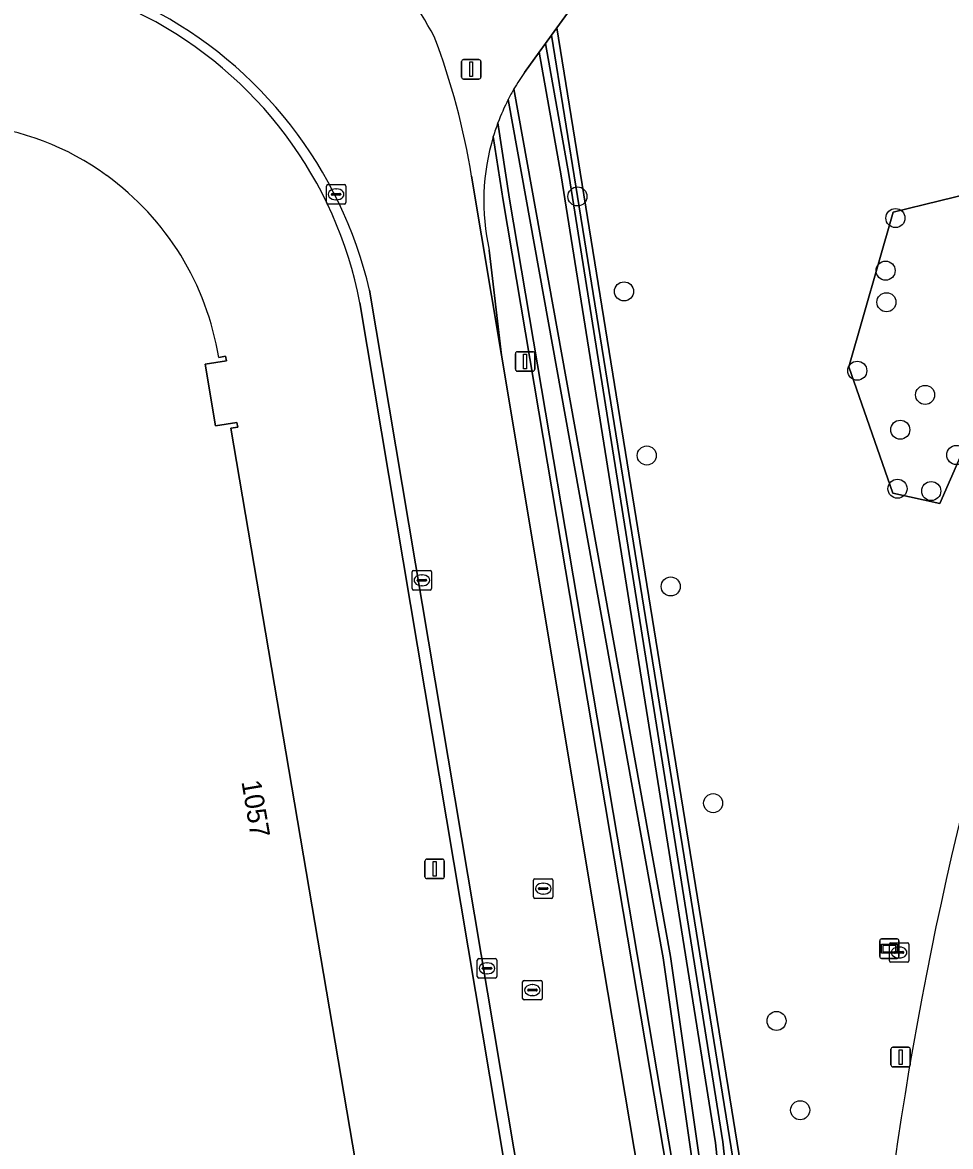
# Model space of a CAD drawing. Extents: x 154324 to 155744, y 382937 to 384188.
# Drawn here: x 154972.4 to 155020, y 383822.2 to 383879.9 of the extents above; entities that cross this region are included whole.
import ezdxf

# ---------------------------------------------------------------- set-up
doc = ezdxf.new("R2010")
doc.units = 0
for name, color, linetype in [('IMGEO_Boom', 7, 'Continuous'), ('IMGEO_Brandkraan', 7, 'Continuous'), ('IMGEO_Fietspad_gesloten', 7, 'Continuous'), ('IMGEO_Gemengd_bos', 7, 'Continuous'), ('IMGEO_Groenvoorziening', 7, 'Continuous'), ('IMGEO_Kolk', 7, 'Continuous'), ('IMGEO_Lichtmast', 7, 'Continuous'), ('IMGEO_Loofbos', 7, 'Continuous'), ('IMGEO_Oever', 7, 'Continuous'), ('IMGEO_Pand', 7, 'Continuous'), ('IMGEO_Pand_nummerreeks', 7, 'Continuous'), ('IMGEO_Rijbaan_lokaal_gesloten', 7, 'Continuous'), ('IMGEO_Rijbaan_lokaal_open', 7, 'Continuous'), ('IMGEO_Rioolput', 7, 'Continuous'), ('IMGEO_Verklikker', 7, 'Continuous'), ('IMGEO_Voetpad_open', 7, 'Continuous'), ('IMGEO_Waterloop', 7, 'Continuous')]:
    doc.layers.add(name, color=color, linetype=linetype)

msp = doc.modelspace()

# ---------------------------------------------------------------- linework, layer by layer
at = {"layer": 'IMGEO_Boom'}
for centre in [(155000.837, 383870.939), (155017.141, 383869.83), (155016.636, 383867.133), (155003.225, 383866.07), (155016.679, 383865.514), (155015.183, 383862.004), (155018.661, 383860.763), (155017.388, 383858.977), (155004.392, 383857.656), (155020.259, 383857.681), (155017.246, 383855.953), (155018.975, 383855.834), (155005.618, 383850.94), (155007.794, 383839.829), (155011.045, 383828.66), (155012.255, 383824.082)]:
    msp.add_circle(centre, 0.489, dxfattribs=at)
at = {"layer": 'IMGEO_Brandkraan'}
for p, q in [((155016.828, 383831.745), (155016.828, 383832.597)), ((155016.903, 383832.671), (155017.755, 383832.671)), ((155017.829, 383832.597), (155017.829, 383831.745)), ((155017.087, 383832.165), (155017.087, 383832.177)), ((155017.525, 383832.128), (155017.127, 383832.128)), ((155017.13, 383832.214), (155017.528, 383832.214)), ((155017.316, 383832.451), (155017.341, 383832.451)), ((155017.571, 383832.177), (155017.571, 383832.165)), ((155017.755, 383831.671), (155016.903, 383831.671)), ((155017.339, 383831.891), (155017.314, 383831.891))]:
    msp.add_line(p, q, dxfattribs=at)
for points in [[(155016.828, 383831.745), (155016.828, 383832.597)], [(155016.903, 383832.671), (155017.755, 383832.671)], [(155017.829, 383832.597), (155017.829, 383831.745)], [(155017.755, 383831.671), (155016.903, 383831.671)]]:
    msp.add_lwpolyline(points, dxfattribs=at)
for centre, radius, start, end in [((155016.905, 383832.595), 0.0765, 91.55205, 178.44795), ((155016.905, 383832.595), 0.0765, 91.55205, 178.44795), ((155017.753, 383832.595), 0.0765, 1.55205, 88.44795), ((155017.753, 383832.595), 0.0765, 1.55205, 88.44795), ((155017.127, 383832.174), 0.0403, 85.87752, 175.75265), ((155017.124, 383832.164), 0.0366, 178.93798, 274.71019), ((155017.528, 383832.171), 0.043, 264.86636, 352.45326), ((155017.532, 383832.176), 0.0386, 1.73085, 96.63898), ((155016.905, 383831.747), 0.0765, 181.55205, 268.44795), ((155016.905, 383831.747), 0.0765, 181.55205, 268.44795), ((155017.753, 383831.747), 0.0765, 271.55205, 358.44795), ((155017.753, 383831.747), 0.0765, 271.55205, 358.44795)]:
    msp.add_arc(centre, radius, start, end, dxfattribs=at)
for centre, major_axis, ratio, start_param, end_param in [((155017.315, 383832.171), (-0.387, 0.002), 0.722429, 4.712389, 7.853982), ((155017.34, 383832.171), (-0.39, 0.002), 0.717154, 1.570796, 4.712389)]:
    msp.add_ellipse(centre, major_axis=major_axis, ratio=ratio, start_param=start_param, end_param=end_param, dxfattribs=at)
at = {"layer": 'IMGEO_Fietspad_gesloten'}
for centre, radius, start, end in [((155068.256, 383897.466), 48.743, 181.03851, 207.95634), ((155205.608, 383794.513), 190.42, 159.9547, 171.93294)]:
    msp.add_arc(centre, radius, start, end, dxfattribs=at)
at = {"layer": 'IMGEO_Gemengd_bos'}
for points in [[(155007.915, 383822.409), (155000.011, 383871.994), (154998.88, 383878.344), (154998.126, 383877.302)], [(154997.582, 383876.452), (155005.612, 383831.964), (155009.111, 383807.437), (155008.833, 383813.728), (155008.825, 383813.835), (155007.915, 383822.409)]]:
    msp.add_lwpolyline(points, dxfattribs=at)
msp.add_arc((155007.047, 383870.993), 10.927, 144.73392, 150.02759, dxfattribs=at)
at = {"layer": 'IMGEO_Groenvoorziening'}
for points in [[(155004.825, 383886.546), (155002.919, 383883.925), (155001.914, 383882.537), (154999.781, 383879.589), (155010.405, 383813.833), (155010.749, 383800.586)], [(155008.779, 383799.869), (155006.822, 383812.702), (154997.022, 383870.738), (154996.525, 383874.017)], [(154996.312, 383868.192), (154996.943, 383862.793), (155002.174, 383831.432), (155007.976, 383797.016), (155010.285, 383783.102), (155010.136, 383783.072), (155013.373, 383763.974), (155014.065, 383763.349), (155014.521, 383763.048)]]:
    msp.add_lwpolyline(points, dxfattribs=at)
msp.add_lwpolyline([(155025.672, 383869.465), (155019.414, 383855.191), (155016.999, 383855.716), (155014.751, 383862.196), (155017.019, 383870.138), (155024.143, 383871.87)], close=True, dxfattribs=at)
for centre, radius, start, end in [((155068.256, 383897.466), 48.743, 181.03851, 207.95634), ((155007.497, 383870.699), 11.462, 163.17576, 192.63589), ((155205.608, 383794.513), 190.42, 159.9547, 171.93294)]:
    msp.add_arc(centre, radius, start, end, dxfattribs=at)
at = {"layer": 'IMGEO_Kolk'}
for p, q in [((154987.965, 383870.621), (154987.965, 383871.473)), ((154988.04, 383871.547), (154988.892, 383871.547)), ((154988.453, 383871.327), (154988.478, 383871.327)), ((154988.966, 383871.473), (154988.966, 383870.621)), ((154988.892, 383870.547), (154988.04, 383870.547)), ((154988.224, 383871.041), (154988.224, 383871.053)), ((154988.662, 383871.004), (154988.264, 383871.004)), ((154988.267, 383871.09), (154988.665, 383871.09)), ((154988.476, 383870.767), (154988.451, 383870.767)), ((154988.708, 383871.053), (154988.708, 383871.041)), ((154992.361, 383850.831), (154992.361, 383851.683)), ((154992.436, 383851.757), (154993.288, 383851.757)), ((154992.849, 383851.537), (154992.874, 383851.537)), ((154993.362, 383851.683), (154993.362, 383850.831)), ((154992.62, 383851.251), (154992.62, 383851.263)), ((154993.058, 383851.214), (154992.66, 383851.214)), ((154992.663, 383851.3), (154993.061, 383851.3)), ((154992.872, 383850.977), (154992.847, 383850.977)), ((154993.104, 383851.263), (154993.104, 383851.251)), ((154993.288, 383850.757), (154992.436, 383850.757)), ((154995.701, 383830.932), (154995.701, 383831.784)), ((154995.776, 383831.858), (154996.628, 383831.858)), ((154995.96, 383831.352), (154995.96, 383831.364)), ((154996.003, 383831.401), (154996.401, 383831.401)), ((154996.189, 383831.638), (154996.214, 383831.638)), ((154996.444, 383831.364), (154996.444, 383831.352)), ((154996.702, 383831.784), (154996.702, 383830.932)), ((154996.628, 383830.858), (154995.776, 383830.858)), ((154996.398, 383831.315), (154996, 383831.315)), ((154996.212, 383831.078), (154996.187, 383831.078))]:
    msp.add_line(p, q, dxfattribs=at)
for points in [[(154987.965, 383870.621), (154987.965, 383871.473)], [(154988.04, 383871.547), (154988.892, 383871.547)], [(154988.966, 383871.473), (154988.966, 383870.621)], [(154988.892, 383870.547), (154988.04, 383870.547)], [(154992.361, 383850.831), (154992.361, 383851.683)], [(154992.436, 383851.757), (154993.288, 383851.757)], [(154993.362, 383851.683), (154993.362, 383850.831)], [(154993.288, 383850.757), (154992.436, 383850.757)], [(154995.701, 383830.932), (154995.701, 383831.784)], [(154995.776, 383831.858), (154996.628, 383831.858)], [(154996.702, 383831.784), (154996.702, 383830.932)], [(154996.628, 383830.858), (154995.776, 383830.858)]]:
    msp.add_lwpolyline(points, dxfattribs=at)
for centre, radius, start, end in [((154988.042, 383871.471), 0.0765, 91.55205, 178.44795), ((154988.042, 383871.471), 0.0765, 91.55205, 178.44795), ((154988.89, 383871.471), 0.0765, 1.55205, 88.44795), ((154988.89, 383871.471), 0.0765, 1.55205, 88.44795), ((154988.042, 383870.623), 0.0765, 181.55205, 268.44795), ((154988.042, 383870.623), 0.0765, 181.55205, 268.44795), ((154988.264, 383871.05), 0.0403, 85.87752, 175.75265), ((154988.261, 383871.04), 0.0366, 178.93798, 274.71019), ((154988.665, 383871.047), 0.043, 264.86636, 352.45326), ((154988.669, 383871.052), 0.0386, 1.73085, 96.63898), ((154988.89, 383870.623), 0.0765, 271.55205, 358.44795), ((154988.89, 383870.623), 0.0765, 271.55205, 358.44795), ((154992.438, 383851.681), 0.0765, 91.55205, 178.44795), ((154992.438, 383851.681), 0.0765, 91.55205, 178.44795), ((154993.286, 383851.681), 0.0765, 1.55205, 88.44795), ((154993.286, 383851.681), 0.0765, 1.55205, 88.44795), ((154992.66, 383851.26), 0.0403, 85.87752, 175.75265), ((154992.657, 383851.25), 0.0366, 178.93798, 274.71019), ((154993.061, 383851.257), 0.043, 264.86636, 352.45326), ((154993.065, 383851.262), 0.0386, 1.73085, 96.63898), ((154992.438, 383850.833), 0.0765, 181.55205, 268.44795), ((154992.438, 383850.833), 0.0765, 181.55205, 268.44795), ((154993.286, 383850.833), 0.0765, 271.55205, 358.44795), ((154993.286, 383850.833), 0.0765, 271.55205, 358.44795), ((154995.778, 383831.782), 0.0765, 91.55205, 178.44795), ((154995.778, 383831.782), 0.0765, 91.55205, 178.44795), ((154996, 383831.361), 0.0403, 85.87752, 175.75265), ((154995.997, 383831.351), 0.0366, 178.93798, 274.71019), ((154996.401, 383831.358), 0.043, 264.86636, 352.45326), ((154996.405, 383831.363), 0.0386, 1.73085, 96.63898), ((154996.626, 383831.782), 0.0765, 1.55205, 88.44795), ((154996.626, 383831.782), 0.0765, 1.55205, 88.44795), ((154995.778, 383830.934), 0.0765, 181.55205, 268.44795), ((154995.778, 383830.934), 0.0765, 181.55205, 268.44795), ((154996.626, 383830.934), 0.0765, 271.55205, 358.44795), ((154996.626, 383830.934), 0.0765, 271.55205, 358.44795)]:
    msp.add_arc(centre, radius, start, end, dxfattribs=at)
for centre, major_axis, ratio, start_param, end_param in [((154988.452, 383871.047), (-0.387, 0.002), 0.722429, 4.712389, 7.853982), ((154988.477, 383871.047), (-0.39, 0.002), 0.717154, 1.570796, 4.712389), ((154992.848, 383851.257), (-0.387, 0.002), 0.722429, 4.712389, 7.853982), ((154992.873, 383851.257), (-0.39, 0.002), 0.717154, 1.570796, 4.712389), ((154996.188, 383831.358), (-0.387, 0.002), 0.722429, 4.712389, 7.853982), ((154996.213, 383831.358), (-0.39, 0.002), 0.717154, 1.570796, 4.712389)]:
    msp.add_ellipse(centre, major_axis=major_axis, ratio=ratio, start_param=start_param, end_param=end_param, dxfattribs=at)
at = {"layer": 'IMGEO_Lichtmast'}
for p, q in [((154994.895, 383877.06), (154994.895, 383877.86)), ((154994.895, 383877.86), (154994.895, 383877.06)), ((154994.995, 383877.96), (154995.785, 383877.96)), ((154995.785, 383877.96), (154994.995, 383877.96)), ((154995.885, 383877.86), (154995.885, 383877.06)), ((154995.885, 383877.06), (154995.885, 383877.86)), ((154995.785, 383876.96), (154994.995, 383876.96)), ((154994.995, 383876.96), (154995.785, 383876.96)), ((154997.661, 383862.076), (154997.661, 383862.876)), ((154997.661, 383862.876), (154997.661, 383862.076)), ((154997.761, 383862.976), (154998.551, 383862.976)), ((154998.551, 383862.976), (154997.761, 383862.976)), ((154998.651, 383862.876), (154998.651, 383862.076)), ((154998.651, 383862.076), (154998.651, 383862.876)), ((154998.551, 383861.976), (154997.761, 383861.976)), ((154997.761, 383861.976), (154998.551, 383861.976)), ((154993.022, 383836.057), (154993.022, 383836.857)), ((154993.022, 383836.857), (154993.022, 383836.057)), ((154993.122, 383836.957), (154993.912, 383836.957)), ((154993.912, 383836.957), (154993.122, 383836.957)), ((154994.012, 383836.857), (154994.012, 383836.057)), ((154994.012, 383836.057), (154994.012, 383836.857)), ((154993.912, 383835.957), (154993.122, 383835.957)), ((154993.122, 383835.957), (154993.912, 383835.957)), ((155017.012, 383827.308), (155017.802, 383827.308)), ((155017.802, 383827.308), (155017.012, 383827.308)), ((155016.912, 383826.408), (155016.912, 383827.208)), ((155016.912, 383827.208), (155016.912, 383826.408)), ((155017.902, 383827.208), (155017.902, 383826.408)), ((155017.902, 383826.408), (155017.902, 383827.208)), ((155017.802, 383826.308), (155017.012, 383826.308)), ((155017.012, 383826.308), (155017.802, 383826.308))]:
    msp.add_line(p, q, dxfattribs=at)
for points in [[(154995.315, 383877.835), (154995.465, 383877.835), (154995.465, 383877.085), (154995.315, 383877.085), (154995.315, 383877.835)], [(154998.081, 383862.851), (154998.231, 383862.851), (154998.231, 383862.101), (154998.081, 383862.101), (154998.081, 383862.851)], [(154993.442, 383836.832), (154993.592, 383836.832), (154993.592, 383836.082), (154993.442, 383836.082), (154993.442, 383836.832)], [(155017.332, 383827.183), (155017.482, 383827.183), (155017.482, 383826.433), (155017.332, 383826.433), (155017.332, 383827.183)]]:
    msp.add_lwpolyline(points, dxfattribs=at)
for centre, start, end in [((154994.995, 383877.86), 90, 180), ((154994.995, 383877.86), 90, 180), ((154995.785, 383877.86), 0, 90), ((154995.785, 383877.86), 360, 90), ((154994.995, 383877.06), 180, 270), ((154994.995, 383877.06), 180, 270), ((154995.785, 383877.06), 270, 0), ((154995.785, 383877.06), 270, 0), ((154997.761, 383862.876), 90, 180), ((154997.761, 383862.876), 90, 180), ((154998.551, 383862.876), 0, 90), ((154998.551, 383862.876), 360, 90), ((154997.761, 383862.076), 180, 270), ((154997.761, 383862.076), 180, 270), ((154998.551, 383862.076), 270, 0), ((154998.551, 383862.076), 270, 0), ((154993.122, 383836.857), 90, 180), ((154993.122, 383836.857), 90, 180), ((154993.912, 383836.857), 0, 90), ((154993.912, 383836.857), 360, 90), ((154993.122, 383836.057), 180, 270), ((154993.122, 383836.057), 180, 270), ((154993.912, 383836.057), 270, 0), ((154993.912, 383836.057), 270, 0), ((155017.012, 383827.208), 90, 180), ((155017.012, 383827.208), 90, 180), ((155017.802, 383827.208), 0, 90), ((155017.802, 383827.208), 360, 90), ((155017.012, 383826.408), 180, 270), ((155017.012, 383826.408), 180, 270), ((155017.802, 383826.408), 270, 0), ((155017.802, 383826.408), 270, 0)]:
    msp.add_arc(centre, 0.1, start, end, dxfattribs=at)
at = {"layer": 'IMGEO_Loofbos'}
msp.add_lwpolyline([(155025.672, 383869.465), (155024.143, 383871.87), (155017.019, 383870.138), (155014.751, 383862.196), (155016.999, 383855.716), (155019.414, 383855.191)], close=True, dxfattribs=at)
at = {"layer": 'IMGEO_Oever'}
for points in [[(155010.749, 383800.586), (155010.405, 383813.833), (154999.781, 383879.589), (154999.501, 383879.202), (155000.837, 383870.939), (155010.067, 383813.801), (155010.409, 383800.612)], [(154997.285, 383875.907), (155005.228, 383831.902), (155008.867, 383806.395), (155009.545, 383806.425), (155009.221, 383813.751), (155009.212, 383813.87), (155008.3, 383822.46), (155000.394, 383872.059), (154999.197, 383878.781), (154998.88, 383878.344), (155000.011, 383871.994), (155007.915, 383822.409), (155008.825, 383813.835), (155008.833, 383813.728), (155009.111, 383807.437), (155005.612, 383831.964), (154997.582, 383876.452)], [(155009.11, 383799.946), (155007.157, 383812.756), (154997.357, 383870.792), (154996.761, 383874.717)], [(154996.525, 383874.017), (154997.022, 383870.738), (155006.822, 383812.702), (155008.779, 383799.869)]]:
    msp.add_lwpolyline(points, dxfattribs=at)
for centre, radius, start, end in [((155008.585, 383870.102), 12.704, 150.01187, 152.81142), ((155006.86, 383870.922), 10.788, 159.40686, 163.3308)]:
    msp.add_arc(centre, radius, start, end, dxfattribs=at)
at = {"layer": 'IMGEO_Pand'}
for points in [[(154962.788, 383873.403), (154930.221, 383858.416), (154936.2, 383845.476), (154938.531, 383840.433), (154922.044, 383832.788), (154921.562, 383832.565), (154925.972, 383806.919), (154925.989, 383806.82), (154990.078, 383817.772), (154990.053, 383817.92), (154983.065, 383859.056)], [(154983.065, 383859.056), (154983.42, 383859.114), (154983.382, 383859.351), (154982.276, 383859.173), (154981.758, 383862.33), (154982.843, 383862.511), (154982.803, 383862.747), (154982.447, 383862.688)]]:
    msp.add_lwpolyline(points, dxfattribs=at)
for centre, radius, start, end in [((154968.564, 383860.875), 13.795, 53.84566, 114.75354), ((154968.262, 383860.383), 14.371, 9.2287, 54.03016)]:
    msp.add_arc(centre, radius, start, end, dxfattribs=at)
at = {"layer": 'IMGEO_Rijbaan_lokaal_gesloten'}
for points in [[(154998.126, 383877.302), (154998.88, 383878.344), (154999.197, 383878.781), (154999.501, 383879.202), (154999.781, 383879.589), (155001.914, 383882.537), (155002.919, 383883.925), (155004.825, 383886.546)], [(154990.18, 383866.132), (155008.692, 383756.004), (155014.572, 383756.911), (155014.481, 383757.434), (155013.373, 383763.974), (155010.136, 383783.072), (155010.285, 383783.102), (155007.976, 383797.016), (155002.174, 383831.432), (154996.943, 383862.793), (154995.411, 383871.976)], [(154995.411, 383871.976), (154996.943, 383862.793), (154996.312, 383868.192)]]:
    msp.add_lwpolyline(points, dxfattribs=at)
for centre, radius, start, end in [((154973.044, 383868.176), 23.201, 28.19104, 41.12856), ((154973.044, 383868.176), 23.201, 28.19104, 41.12856), ((154968.895, 383861.158), 21.858, 13.15331, 112.43509), ((154959.519, 383866.198), 36.354, 9.14486, 20.84743), ((154959.519, 383866.198), 36.354, 9.14486, 20.84743), ((155007.047, 383870.993), 10.927, 144.73392, 150.02759), ((155008.585, 383870.102), 12.704, 150.01187, 152.81142), ((155007.312, 383870.781), 11.261, 152.92472, 159.54403), ((155006.86, 383870.922), 10.788, 159.40686, 163.3308), ((155007.497, 383870.699), 11.462, 163.17576, 192.63589)]:
    msp.add_arc(centre, radius, start, end, dxfattribs=at)
at = {"layer": 'IMGEO_Rijbaan_lokaal_open'}
msp.add_lwpolyline([(154989.689, 383865.488), (154997.464, 383819.179), (155002.093, 383791.612), (155006.354, 383766.232), (155008.641, 383752.609), (155011.19, 383737.428), (155012.365, 383730.431), (155013.835, 383721.664), (155016.277, 383707.107), (155016.871, 383707.197), (155013.247, 383728.802), (155012.973, 383730.527), (155008.692, 383756.004), (154990.18, 383866.132)], dxfattribs=at)
for centre, radius, start, end in [((154968.895, 383861.158), 21.858, 13.15331, 112.43509), ((154969.058, 383861.488), 21.015, 10.97244, 114.49876)]:
    msp.add_arc(centre, radius, start, end, dxfattribs=at)
at = {"layer": 'IMGEO_Rioolput'}
for p, q in [((154998.658, 383835.946), (154999.51, 383835.946)), ((154998.583, 383835.02), (154998.583, 383835.872)), ((154998.842, 383835.44), (154998.842, 383835.452)), ((154999.28, 383835.403), (154998.882, 383835.403)), ((154998.885, 383835.489), (154999.283, 383835.489)), ((154999.071, 383835.726), (154999.096, 383835.726)), ((154999.326, 383835.452), (154999.326, 383835.44)), ((154999.584, 383835.872), (154999.584, 383835.02)), ((154999.51, 383834.946), (154998.658, 383834.946)), ((154999.094, 383835.166), (154999.069, 383835.166)), ((154998.029, 383829.816), (154998.029, 383830.668)), ((154998.104, 383830.742), (154998.956, 383830.742)), ((154998.288, 383830.236), (154998.288, 383830.248)), ((154998.726, 383830.199), (154998.328, 383830.199)), ((154998.331, 383830.285), (154998.729, 383830.285)), ((154998.517, 383830.522), (154998.542, 383830.522)), ((154998.772, 383830.248), (154998.772, 383830.236)), ((154999.03, 383830.668), (154999.03, 383829.816)), ((154998.956, 383829.742), (154998.104, 383829.742)), ((154998.54, 383829.962), (154998.515, 383829.962))]:
    msp.add_line(p, q, dxfattribs=at)
for points in [[(154998.658, 383835.946), (154999.51, 383835.946)], [(154998.583, 383835.02), (154998.583, 383835.872)], [(154999.584, 383835.872), (154999.584, 383835.02)], [(154999.51, 383834.946), (154998.658, 383834.946)], [(154998.029, 383829.816), (154998.029, 383830.668)], [(154998.104, 383830.742), (154998.956, 383830.742)], [(154999.03, 383830.668), (154999.03, 383829.816)], [(154998.956, 383829.742), (154998.104, 383829.742)]]:
    msp.add_lwpolyline(points, dxfattribs=at)
for centre, radius, start, end in [((154998.66, 383835.87), 0.0765, 91.55205, 178.44795), ((154998.66, 383835.87), 0.0765, 91.55205, 178.44795), ((154999.508, 383835.87), 0.0765, 1.55205, 88.44795), ((154999.508, 383835.87), 0.0765, 1.55205, 88.44795), ((154998.882, 383835.449), 0.0403, 85.87752, 175.75265), ((154998.879, 383835.439), 0.0366, 178.93798, 274.71019), ((154999.283, 383835.446), 0.043, 264.86636, 352.45326), ((154999.287, 383835.451), 0.0386, 1.73085, 96.63898), ((154998.66, 383835.022), 0.0765, 181.55205, 268.44795), ((154998.66, 383835.022), 0.0765, 181.55205, 268.44795), ((154999.508, 383835.022), 0.0765, 271.55205, 358.44795), ((154999.508, 383835.022), 0.0765, 271.55205, 358.44795), ((154998.106, 383830.666), 0.0765, 91.55205, 178.44795), ((154998.106, 383830.666), 0.0765, 91.55205, 178.44795), ((154998.328, 383830.245), 0.0403, 85.87752, 175.75265), ((154998.325, 383830.235), 0.0366, 178.93798, 274.71019), ((154998.729, 383830.242), 0.043, 264.86636, 352.45326), ((154998.733, 383830.247), 0.0386, 1.73085, 96.63898), ((154998.954, 383830.666), 0.0765, 1.55205, 88.44795), ((154998.954, 383830.666), 0.0765, 1.55205, 88.44795), ((154998.106, 383829.818), 0.0765, 181.55205, 268.44795), ((154998.106, 383829.818), 0.0765, 181.55205, 268.44795), ((154998.954, 383829.818), 0.0765, 271.55205, 358.44795), ((154998.954, 383829.818), 0.0765, 271.55205, 358.44795)]:
    msp.add_arc(centre, radius, start, end, dxfattribs=at)
for centre, major_axis, ratio, start_param, end_param in [((154999.07, 383835.446), (-0.387, 0.002), 0.722429, 4.712389, 7.853982), ((154999.095, 383835.446), (-0.39, 0.002), 0.717154, 1.570796, 4.712389), ((154998.516, 383830.242), (-0.387, 0.002), 0.722429, 4.712389, 7.853982), ((154998.541, 383830.242), (-0.39, 0.002), 0.717154, 1.570796, 4.712389)]:
    msp.add_ellipse(centre, major_axis=major_axis, ratio=ratio, start_param=start_param, end_param=end_param, dxfattribs=at)
at = {"layer": 'IMGEO_Verklikker'}
for p, q in [((155016.332, 383831.969), (155016.332, 383832.769)), ((155016.332, 383832.769), (155016.332, 383831.969)), ((155016.432, 383832.869), (155017.222, 383832.869)), ((155017.222, 383832.869), (155016.432, 383832.869)), ((155017.322, 383832.769), (155017.322, 383831.969)), ((155017.322, 383831.969), (155017.322, 383832.769)), ((155017.222, 383831.869), (155016.432, 383831.869)), ((155016.432, 383831.869), (155017.222, 383831.869))]:
    msp.add_line(p, q, dxfattribs=at)
for points in [[(155016.433, 383832.601), (155017.221, 383832.601), (155017.221, 383832.137), (155016.433, 383832.137), (155016.433, 383832.601)], [(155016.498, 383832.536), (155016.498, 383832.202), (155017.156, 383832.202), (155017.156, 383832.536), (155016.498, 383832.536)]]:
    msp.add_lwpolyline(points, dxfattribs=at)
for centre, start, end in [((155016.432, 383832.769), 90, 180), ((155016.432, 383832.769), 90, 180), ((155017.222, 383832.769), 0, 90), ((155017.222, 383832.769), 360, 90), ((155016.432, 383831.969), 180, 270), ((155016.432, 383831.969), 180, 270), ((155017.222, 383831.969), 270, 0), ((155017.222, 383831.969), 270, 0)]:
    msp.add_arc(centre, 0.1, start, end, dxfattribs=at)
at = {"layer": 'IMGEO_Voetpad_open'}
msp.add_lwpolyline([(154982.447, 383862.688), (154982.803, 383862.747), (154982.843, 383862.511), (154981.758, 383862.33), (154982.276, 383859.173), (154983.382, 383859.351), (154983.42, 383859.114), (154983.065, 383859.056), (154990.053, 383817.92), (154997.464, 383819.179), (154989.689, 383865.488)], dxfattribs=at)
for centre, radius, start, end in [((154969.058, 383861.488), 21.015, 10.97244, 114.49876), ((154968.564, 383860.875), 13.795, 53.84566, 114.75354), ((154968.262, 383860.383), 14.371, 9.2287, 54.03016)]:
    msp.add_arc(centre, radius, start, end, dxfattribs=at)
at = {"layer": 'IMGEO_Waterloop'}
for points in [[(155010.409, 383800.612), (155010.067, 383813.801), (155000.837, 383870.939), (154999.501, 383879.202), (154999.197, 383878.781), (155000.394, 383872.059), (155008.3, 383822.46), (155009.212, 383813.87), (155009.221, 383813.751), (155009.545, 383806.425), (155008.867, 383806.395), (155005.228, 383831.902), (154997.285, 383875.907)], [(154996.761, 383874.717), (154997.357, 383870.792), (155007.157, 383812.756), (155009.11, 383799.946)]]:
    msp.add_lwpolyline(points, dxfattribs=at)
msp.add_arc((155007.312, 383870.781), 11.261, 152.92472, 159.54403, dxfattribs=at)

# ---------------------------------------------------------------- texts
at = {"layer": 'IMGEO_Pand_nummerreeks'}
msp.add_text('1057', height=1, rotation=279.64267, dxfattribs=at).set_placement((154983.608, 383840.93))

doc.saveas('drawing.dxf')
